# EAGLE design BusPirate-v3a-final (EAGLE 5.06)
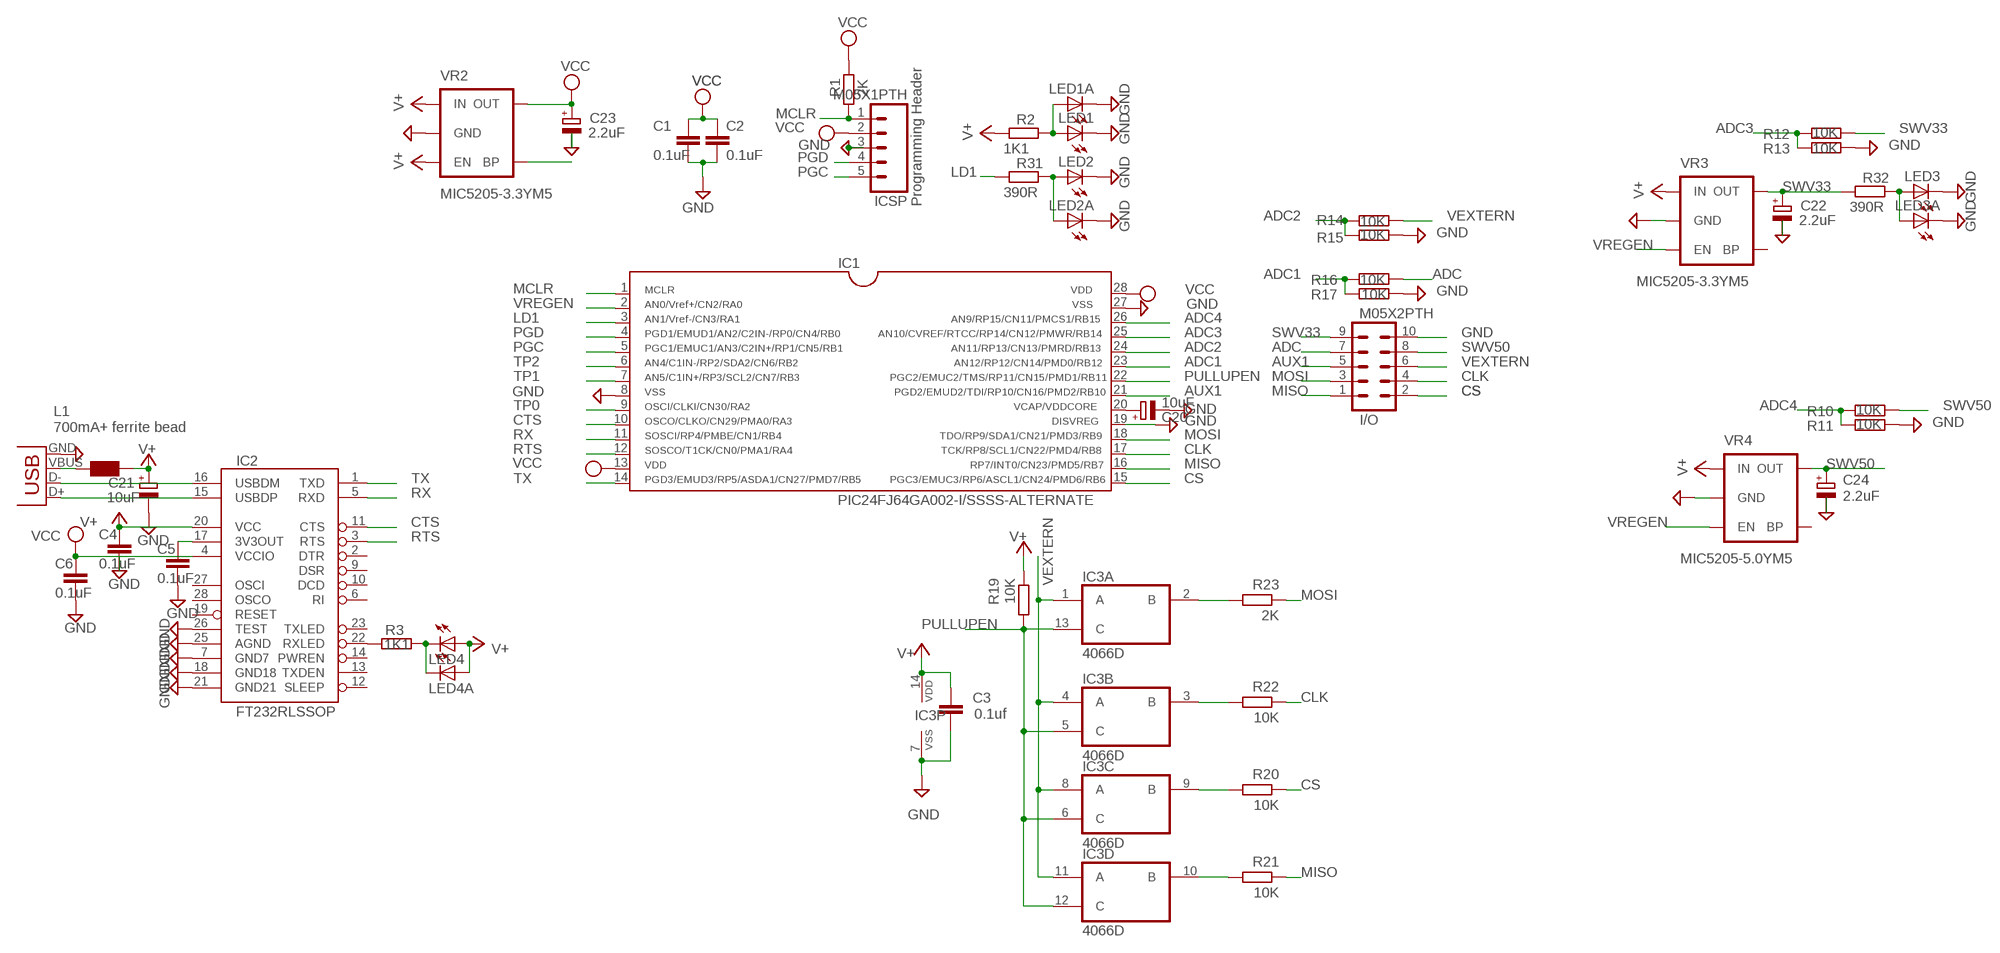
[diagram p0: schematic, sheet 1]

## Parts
C1  0.1uF  C-EUC0805  [C0805]
C2  0.1uF  C-EUC0805  [C0805]
C3  0.1uf  C-EUC0805  [C0805]
C4  0.1uF  C-EUC0805  [C0805]
C5  0.1uF  C-EUC0805  [C0805]
C6  0.1uF  C-EUC0805  [C0805]
C20  10uF  CPOL-EUSMCA  [SMC_A]
C21  10uF  CPOL-EUSMCA  [SMC_A]
C22  2.2uF  CPOL-EUSMCA  [SMC_A]
C23  2.2uF  CPOL-EUSMCA  [SMC_A]
C24  2.2uF  CPOL-EUSMCA  [SMC_A]
I/O  M05X2PTH  [AVR_ICSP]
IC1  PIC24FJ64GA002-I/SSSS-ALTERNATE  [SSOP28DB]
IC2  FT232RLSSOP  [SSOP28DB]
IC3  4066D  [SO14]
ICSP  M05X1PTH  M05  [1X05]
J1  USBSMD  [USB-MINIB]
L1  700mA+ ferrite bead  WE-KIL_0805  [WE-KI_0805_B]
LED1  LEDCHIP-LED0805  [CHIP-LED0805]
LED1A  LEDCHIP-LED0805  [CHIP-LED0805]
LED2  LEDCHIP-LED0805  [CHIP-LED0805]
LED2A  LEDCHIP-LED0805  [CHIP-LED0805]
LED3  LEDCHIP-LED0805  [CHIP-LED0805]
LED3A  LEDCHIP-LED0805  [CHIP-LED0805]
LED4  LEDCHIP-LED0805  [CHIP-LED0805]
LED4A  LEDCHIP-LED0805  [CHIP-LED0805]
R1  2K  R-EU_R0805  [R0805]
R2  1K1  R-EU_M0805  [M0805]
R3  1K1  R-EU_M0805  [M0805]
R10  10K  R-EU_M0805  [M0805]
R11  10K  R-EU_M0805  [M0805]
R12  10K  R-EU_M0805  [M0805]
R13  10K  R-EU_M0805  [M0805]
R14  10K  R-EU_M0805  [M0805]
R15  10K  R-EU_M0805  [M0805]
R16  10K  R-EU_M0805  [M0805]
R17  10K  R-EU_M0805  [M0805]
R19  10K  R-EU_R0805  [R0805]
R20  10K  R-EU_R0805  [R0805]
R21  10K  R-EU_R0805  [R0805]
R22  10K  R-EU_R0805  [R0805]
R23  2K  R-EU_R0805  [R0805]
R31  390R  R-EU_M0805  [M0805]
R32  390R  R-EU_M0805  [M0805]
VR2  MIC5205-3.3YM5  V_REG_LDOSMD  [SOT23-5]
VR3  MIC5205-3.3YM5  V_REG_LDOSMD  [SOT23-5]
VR4  MIC5205-5.0YM5  V_REG_LDOSMD  [SOT23-5]

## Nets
$N26: J1.VBUS L1.2
ADC: I/O.7 R16.1
ADC1: IC1.23 R16.2 R17.2
ADC2: IC1.24 R14.2 R15.2
ADC3: IC1.25 R12.2 R13.2
ADC4: IC1.26 R10.2 R11.2
AUX1: I/O.5 IC1.21
CLK: I/O.4 IC1.17 R22.1
CS: I/O.2 IC1.15 R20.1
CTS: IC1.10 IC2.11(CTS)
GND: C1.2 C2.2 C3.2 C4.2 C5.2 C6.2 C20.- C21.- C22.- C23.- C24.- I/O.10 IC1.8 IC1.19 IC1.27 IC2.7(GND7) IC2.18(GND18) IC2.21(GND21) IC2.25(AGND) IC2.26(TEST) IC3.7(P:VSS) ICSP.3 J1.GND LED1.C LED1A.C LED2.C LED2A.C LED3.C LED3A.C R11.1 R13.1 R15.1 R17.1 VR2.2(GND) VR3.2(GND) VR4.2(GND)
LD1: IC1.3 R31.2
MCLR: IC1.1 ICSP.1 R1.1
MISO: I/O.1 IC1.16 R21.1
MOSI: I/O.3 IC1.18 R23.1
N$1: IC3.2(A:B) R23.2
N$2: IC3.3(B:B) R22.2
N$3: C20.+ IC1.20
N$4: IC3.10(D:B) R21.2
N$5: IC3.9(C:B) R20.2
N$6: LED2.A LED2A.A R31.1
N$7: LED1.A LED1A.A R2.1
N$8: VR2.4(BP)
N$9: C5.1 IC2.17(3V3OUT)
N$11: IC2.22(RXLED) R3.2
N$13: LED4.C LED4A.C R3.1
N$15: IC2.15(USBDP) J1.D+
N$16: IC2.16(USBDM) J1.D-
N$18: LED3.A LED3A.A R32.1
PGC: IC1.5 ICSP.5
PGD: IC1.4 ICSP.4
PULLUPEN: IC1.22 IC3.5(B:C) IC3.6(C:C) IC3.12(D:C) IC3.13(A:C) R19.2
RTS: IC1.12 IC2.3(RTS)
RX: IC1.11 IC2.5(RXD)
SWV33: C22.+ I/O.9 R12.1 R32.2 VR3.5(OUT)
SWV50: C24.+ I/O.8 R10.1 VR4.5(OUT)
TP0: IC1.9
TP1: IC1.7
TP2: IC1.6
TX: IC1.14 IC2.1(TXD)
V+: C3.1 C4.1 C21.+ IC2.20(VCC) IC3.14(P:VDD) L1.1 LED4.A LED4A.A R2.2 R19.1 VR2.1(IN) VR2.3(EN) VR3.1(IN) VR4.1(IN)
VCC: C1.1 C2.1 C6.1 C23.+ IC1.13 IC1.28 IC2.4(VCCIO) ICSP.2 R1.2 VR2.5(OUT)
VEXTERN: I/O.6 IC3.1(A:A) IC3.4(B:A) IC3.8(C:A) IC3.11(D:A) R14.1
VREGEN: IC1.2 VR3.3(EN) VR4.3(EN)
Unconnected: IC2.2(DTR) IC2.6(RI) IC2.9(DSR) IC2.10(DCD) IC2.12(SLEEP) IC2.13(TXDEN) IC2.14(PWREN) IC2.19(RESET) IC2.23(TXLED) IC2.27(OSCI) IC2.28(OSCO) VR3.4(BP) VR4.4(BP)

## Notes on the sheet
- Programming Header

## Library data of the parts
C1-C6 = rcl:C-EU: CAPACITOR, European symbol
C20-C24 = rcl:CPOL-EU: POLARIZED CAPACITOR, European symbol
I/O = SparkFun:M05X2: Header 5x2 Standard 10-pin dual row 0.1" header. Commonly used with AVR-ISP. Use with Spark Fun Electronics SKU: PRT-00778
IC1 = microchip-pic24:PIC24FJ64GA002-I/SS
IC2 = SparkFun:FT232RL: USB UART FT232RL 4th Generation USB UART (USB <-> Serial) Controller. Spark Fun Electronics SKU : COM-00650
IC3 = 40xx:4066: Quad bilateral ANALOG SWITCH
ICSP = SparkFun:M05: Header 5 Standard 5-pin 0.1" header. Use with straight break away headers (SKU : PRT-00116), right angle break away headers (PRT-00553), swiss pins (PRT-00743), machine pins (PRT-00117), and female headers (PRT-00115). Molex polarized connector foot print use with SKU : PRT-08230 with associated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
J1 = SparkFun:USB: USB Connectors USB-B-PTH is fully proven SKU : PRT-00139 USB-miniB is fully proven SKU : PRT-00587 USB-A-PCB is untested. USB-A-H is throughly reviewed, but untested. Spark Fun Electronics SKU : PRT-00437 USB-B-SMT is throughly reviewed, but untested. Needs silkscreen touching up. USB-A-S has not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
L1 = wuerth-elektronik:WE-KIL: SMD Wire Wound Ceramic Inductor WE-KIL
LED1 LED1A LED2 LED2A LED3 LED3A LED4 LED4A = led:LED: LED
R1 R2 R19-R23 R31 R32 = rcl:R-EU_: RESISTOR, European symbol
R3 R10-R17 = resistor:R-EU_: RESISTOR, European symbol
VR2-VR4 = SparkFun:V_REG_LDO: Voltage Regulator LDO Standard 150mA LDO voltage regulator in SOT-23 layout. Micrel part MIC5205. BP (by-pass) pin is used to lower output noise with 470pF cap.

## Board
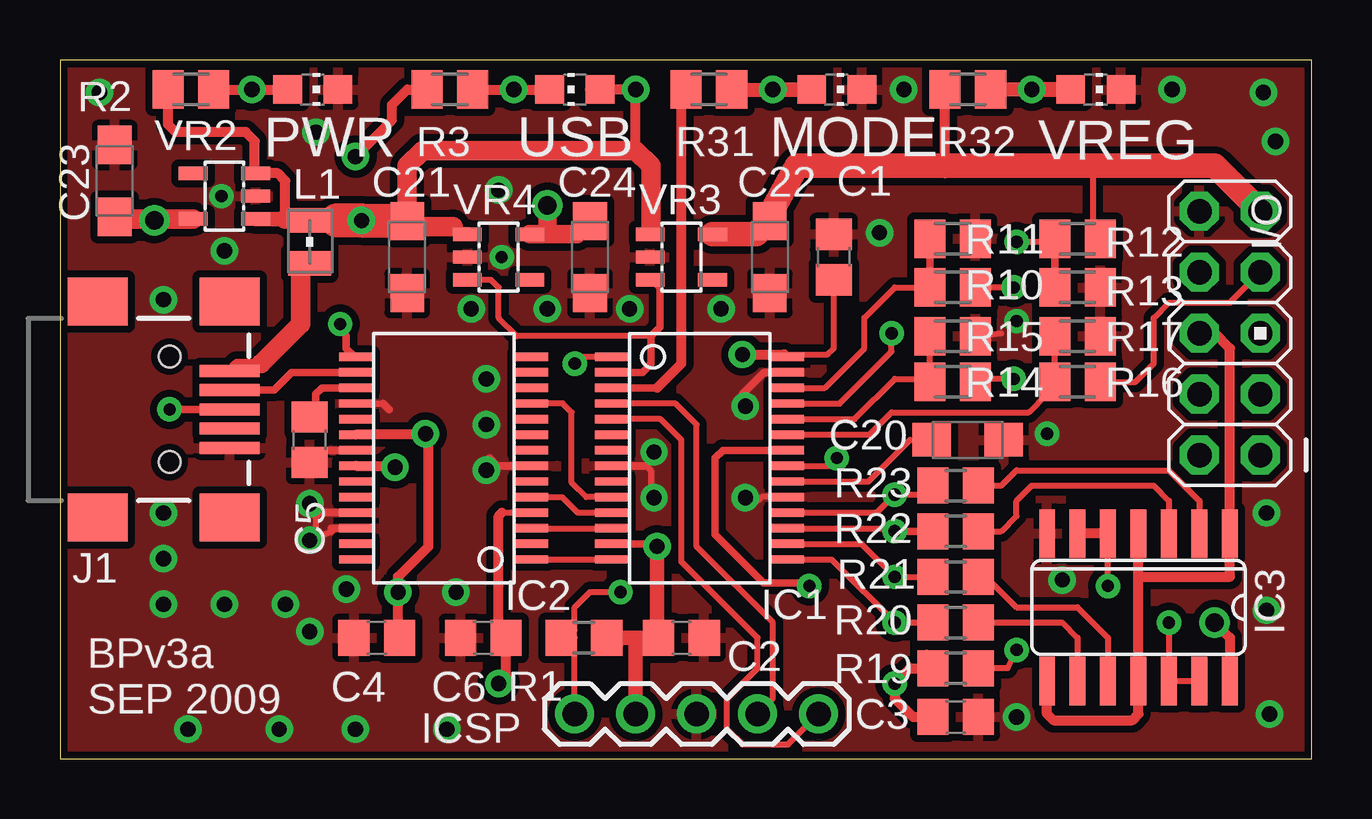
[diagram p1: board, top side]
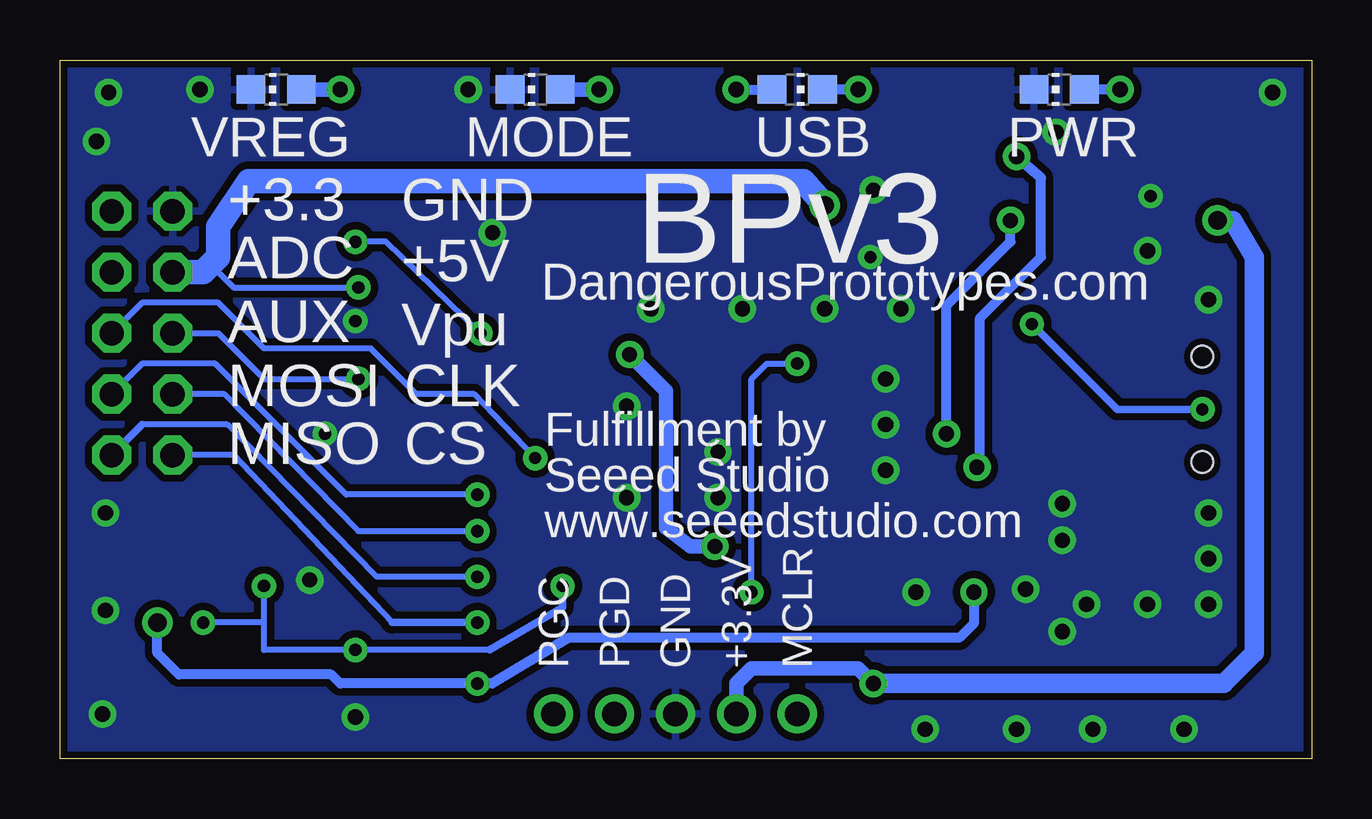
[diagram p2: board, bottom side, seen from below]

Size 52.19 x 29.13 mm. Coordinates in mm from the lower left corner, seen from the top.
Outline: 52.19,0 52.19,29.13 0,29.13 0,0 52.19,0
Copper layers (1*16): Top 0.035mm / dielectric 1.5mm / Bottom 0.035mm
Design rules "SparkFun": minimum track width 8mil, minimum drill 20mil, track to track 8mil, track to pad 8mil, pad to pad 8mil, via to via 8mil, smd to smd 8mil, copper to edge 10mil, drill to drill 8mil, minimum pad ring 12mil, minimum via ring 10mil, stop-mask expansion 4mil, vias tented up to drill 25mil, thermal gap 10mil
tRestrict: area 11.9,9.9 to 12.8,10

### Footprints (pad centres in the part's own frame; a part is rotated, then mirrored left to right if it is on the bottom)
C0805 = smd 1.3 x 1.5: 1 -0.95,0; 2 0.95,0
SMC_A = smd 1.6 x 1.4: + -1.5,0; - 1.5,0
AVR_ICSP = drill 1.016 octagon: 1 -1.27,5.08; 2 1.27,5.08; 3 -1.27,2.54; 4 1.27,2.54; 5 -1.27,0; 6 1.27,0; 7 -1.27,-2.54; 8 1.27,-2.54; 9 -1.27,-5.08; 10 1.27,-5.08
SSOP28DB = smd 0.348 x 1.397: 1 -4.225,-3.656; 2 -3.575,-3.656; 3 -2.925,-3.656; 4 -2.275,-3.656; 5 -1.625,-3.656; 6 -0.975,-3.656; 7 -0.325,-3.656; 8 0.325,-3.656; 9 0.975,-3.656; 10 1.625,-3.656; 11 2.275,-3.656; 12 2.925,-3.656; 13 3.575,-3.656; 14 4.225,-3.656; 15 4.225,3.656; 16 3.575,3.656; 17 2.925,3.656; 18 2.275,3.656; 19 1.625,3.656; 20 0.975,3.656; 21 0.325,3.656; 22 -0.325,3.656; 23 -0.975,3.656; 24 -1.625,3.656; 25 -2.275,3.656; 26 -2.925,3.656; 27 -3.575,3.656; 28 -4.225,3.656
SO14 = smd 0.66 x 2.032: 1 -3.81,-3.073; 2 -2.54,-3.073; 3 -1.27,-3.073; 4 0,-3.073; 5 1.27,-3.073; 6 2.54,-3.073; 7 3.81,-3.073; 8 3.81,3.073; 9 2.54,3.073; 10 1.27,3.073; 11 0,3.073; 12 -1.27,3.073; 13 -2.54,3.073; 14 -3.81,3.073
1X05 = drill 1.016 round: 1 0,0; 2 2.54,0; 3 5.08,0; 4 7.62,0; 5 10.16,0
USB-MINIB = smd 2.5 x 0.5: D+ 2.5,0; D- 2.5,0.8; GND 2.5,-1.6; ID 2.5,-0.8; VBUS 2.5,1.6 | smd 2.5 x 2: GND@1 -3,-4.5; GND@2 -3,4.5; GND@3 2.5,4.5; GND@4 2.5,-4.5 | hole 0.9: 0,2.2; 0,-2.2
WE-KI_0805_B = smd 1.02 x 1.78: 1 -0.89,0; 2 0.89,0
CHIP-LED0805 = smd 1.2 x 1.2: A 0,-1.05; C 0,1.05
R0805 = smd 1.3 x 1.5: 1 -0.95,0; 2 0.95,0
M0805 = smd 1.3 x 1.6: 1 -0.95,0; 2 0.95,0
SOT23-5 = smd 0.55 x 1.2: 1 -0.95,-1.3; 2 0,-1.3; 3 0.95,-1.3; 4 0.95,1.3; 5 -0.95,1.3

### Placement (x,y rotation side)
C1  32.25,20.92 90 top
C2  25.9,5.04 0 top
C3  37.33,1.74 0 top
C4  13.2,5.04 180 top
C5  10.41,13.3 270 top
C6  17.65,5.04 180 top
C20  37.84,13.3 0 top
C21  14.47,20.92 270 top
C22  29.59,20.92 270 top
C23  2.28,24.09 90 top
C24  22.09,20.92 270 top
I/O  48.76,17.74 180 top
IC1  26.66,12.54 270 top
IC2  16,12.54 90 top
IC3  44.95,6.31 180 top
ICSP  21.46,1.87 0 top
J1  4.57,14.57 0 top
L1  10.41,21.55 270 top
LED1  10.54,27.9 270 top
LED1A  10.54,27.9 90 bottom
LED2  32.38,27.9 270 top
LED2A  32.38,27.9 90 bottom
LED3  43.17,27.9 270 top
LED3A  43.17,27.9 90 bottom
LED4  21.46,27.9 90 top
LED4A  21.46,27.9 270 bottom
R1  21.84,5.04 0 top
R2  5.46,27.9 180 top
R3  16.25,27.9 180 top
R10  37.21,19.65 180 top
R11  37.21,21.68 180 top
R12  42.41,21.68 180 top
R13  42.41,19.65 180 top
R14  37.21,15.71 180 top
R15  37.21,17.61 180 top
R16  42.41,15.71 180 top
R17  42.41,17.61 180 top
R19  37.33,3.77 0 top
R20  37.33,5.68 0 top
R21  37.33,7.58 0 top
R22  37.33,9.49 0 top
R23  37.33,11.39 0 top
R31  27.05,27.9 180 top
R32  37.84,27.9 180 top
VR2  6.85,23.46 90 top
VR3  25.9,20.92 270 top
VR4  18.28,20.92 270 top

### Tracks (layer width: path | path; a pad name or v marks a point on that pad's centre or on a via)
$N26
  Top 0.406: 8.38,16.47 7.37,16.47 J1.VBUS
  Top 0.813: L1.2 10.03,20.41 10.03,18.12 8.38,16.47
ADC
  Top 0.254: I/O.7 48.76,19.01 46.22,19.01 45.59,18.38 45.59,16.47 44.83,15.71 R16.1
ADC1
  Top 0.254: R17.2 R16.2 41.46,15.2 41.14,15.2 40.38,14.44 34.67,14.44 33.74,13.51 IC1.23
ADC2
  Top 0.254: R15.2 R14.2 36.26,15.84 34.79,15.84 33.12,14.16 IC1.24
ADC3  (via drill 0.51)
  Top 0.254: v34.67,17.74 34.67,16.98 32.5,14.81 IC1.25 | v39.87,21.55 41.34,21.55 R12.2
  Top 0.305: R13.2 R12.2 41.46,21.87
  Bottom 0.254: v39.87,21.55 38.6,21.55 v34.67,17.74
ADC4
  Top 0.254: IC1.26 31.88,15.46 33.52,17.11 33.52,18.38 34.79,19.65 R10.2
  Top 0.305: R10.2 R11.2
  Top 0.406: R10.2 36.06,19.65
AUX1  (via drill 0.51)
  Top 0.254: IC1.21 32.05,12.21 v32.38,12.54
  Bottom 0.254: I/O.5 48.76,19.01 45.59,19.01 43.68,17.11 39.24,17.11 37.33,15.2 34.92,15.2 v32.38,12.54
CLK  (via drill 0.51)
  Top 0.254: IC1.17 34.67,9.61 v34.79,9.49
  Top 0.305: v34.79,9.49 R22.1
  Bottom 0.254: I/O.4 45.33,15.2 39.75,9.49 v34.79,9.49
CS  (via drill 0.51)
  Top 0.254: R20.1 v34.79,5.68 32.25,8.22 | 32.25,8.22 32.22,8.25 | IC1.15 32.16,8.31 32.25,8.22
  Bottom 0.254: I/O.2 44.95,12.66 38.35,5.68
  Bottom 0.305: v34.79,5.68 38.35,5.68
CTS
  Top 0.254: IC1.10 21.94,10.91 21.33,11.52 21.33,14.44 20.95,14.82 19.66,14.82 IC2.11
GND  (via drill 0.51, 0.64)
  Top 0.254: IC2.18 13.47,14.81 | R15.1 39.24,17.74 | 24.45,12.21 24.63,12.03 24.63,11.01 v24.76,10.88 | IC1.19 29.23,10.91 29.08,10.76 | 10.66,10.12 10.66,9.49 | v10.41,9.11 11.3,9.49
  Top 0.305: IC2.7 18.23,12.21 17.9,12.54 | 13.47,14.81 13.71,14.57 | IC1.27 29.35,16.11 28.44,15.2 28.44,14.82 v28.57,14.69 | IC1.8 24.45,12.21 | IC2.21 10.53,12.86 C5.2 | IC2.25 10.8,10.26 10.66,10.12 | IC2.26 11.3,9.61 11.3,9.49
  other vias: 41.78,7.45 50.29,6.18 50.41,1.87 41.14,13.55 39.87,18.25 34.16,21.93 4.31,10.25 4.31,19.14 35.17,27.9 28.57,10.88 39.87,1.74 50.29,10.25 50.67,25.74 23.74,18.76 20.32,18.76 18.28,23.71 17.14,18.76 17.77,15.84 4.31,6.44 12.31,1.23 4.31,8.34 10.41,10.63 24.76,12.79 10.66,26.12 27.55,18.76 18.41,20.92 5.33,1.23 50.16,27.78 46.35,27.9 9.39,6.44 17.77,12.03 17.77,13.93 6.85,6.44 1.65,27.78 16.5,6.95 10.41,5.3 9.14,1.23 16.12,1.23 11.93,7.07 6.73,23.46 6.85,21.17
  pour Top (isolate 0.305): 0.5,29.17 51.94,29.17 51.94,-0.04 0.5,-0.04
  pour Bottom (isolate 0.305): 0.5,29.17 51.94,29.17 51.94,-0.04 0.5,-0.04
LD1
  Top 0.305: IC1.3 24.89,15.46
  Top 0.406: 24.89,15.46 25.9,16.47 25.9,27.58 R31.2
MCLR  (via drill 0.51)
  Top 0.254: IC1.1 21.75,16.76 v21.46,16.47 | v23.36,6.95 22.09,6.95 21.46,6.31 21.46,5.36 R1.1 21.46,5.04 ICSP.1
  Bottom 0.254: v21.46,16.47 22.73,16.47 23.36,15.84 v23.36,6.95
MISO  (via drill 0.51)
  Top 0.254: v34.79,7.58 R21.1 | v34.79,7.58 34.69,7.69 | IC1.16 33.41,8.96 v34.79,7.58
  Bottom 0.254: 48.76,13.93 45.21,13.93 38.98,7.58 v34.79,7.58
  Bottom 0.305: 48.76,13.93 I/O.1
MOSI  (via drill 0.51)
  Top 0.254: IC1.18 34.04,10.26 v34.79,11.01 36,11.01 R23.1
  Bottom 0.254: I/O.3 48.76,16.47 45.72,16.47 40.25,11.01 v34.79,11.01
N$1
  Top 0.254: IC3.2 47.49,10.76 46.22,12.03 39.87,12.03 39.24,11.39 R23.2
N$2
  Top 0.254: R22.2 39.24,9.49 39.87,10.12 39.87,10.76 40.51,11.39 45.59,11.39 46.22,10.76 IC3.3
N$3
  Top 0.254: IC1.20 33.69,11.56 35.43,13.3 C20.+
N$4
  Top 0.254: R21.2 38.6,7.58 39.87,6.31 42.41,6.31 43.68,5.04 IC3.10
N$5
  Top 0.254: R20.2 41.78,5.68 42.41,5.04 IC3.9
N$6  (via drill 0.64)
  Top 0.406: R31.1 28.16,27.87
  Top 0.61: 28.16,27.87 LED2A.A v29.71,27.9
  Bottom 0.61: v29.71,27.9 LED2A.A
N$7  (via drill 0.64)
  Top 0.406: 6.22,27.9 R2.1 v8,27.9 LED1A.A
  Bottom 0.406: v8,27.9 LED1A.A
N$9
  Top 0.305: IC2.17 10.92,15.46 10.66,15.2 10.66,14.5 C5.1
N$11  (via drill 0.64)
  Top 0.406: 15.36,27.78 R3.2 14.47,27.9 13.84,27.27 13.84,26.63 v12.31,25.11 | IC2.22 13.91,12.21 v13.96,12.15
  Bottom 0.406: v12.31,25.11 11.3,24.22 11.3,20.92 13.84,18.38 13.84,12.15 v13.96,12.15
N$13  (via drill 0.64)
  Top 0.406: R3.1 v18.92,27.9 | v18.92,27.9 LED4A.C v18.92,27.9
  Bottom 0.406: v18.92,27.9 LED4A.C
N$15  (via drill 0.51)
  Top 0.305: v4.57,14.57 J1.D+ | IC2.15 12.28,16.76 11.93,17.11 11.93,17.61 v11.68,18.12
  Bottom 0.305: v4.57,14.57 8.12,14.57 v11.68,18.12
N$16
  Top 0.254: IC2.16 12.36,16.09
  Top 0.305: J1.D- 8.92,15.37 9.67,16.11 IC2.16
N$18  (via drill 0.64)
  Top 0.406: 42.1,27.93 LED3A.A
  Top 0.61: R32.1 42.1,27.93 | LED3A.A v40.51,27.9
  Bottom 0.61: v40.51,27.9 LED3A.A
PGC
  Top 0.254: IC1.5 25.04,14.16 25.9,13.3 25.9,8.22 29.08,5.04 29.08,3.77 27.81,2.5 27.81,1.23 28.44,0.6 30.35,0.6 ICSP.5
PGD
  Top 0.254: IC1.4 25.66,14.81 26.54,13.93 26.54,8.85 29.71,5.68 29.71,2.5 ICSP.4
PULLUPEN  (via drill 0.51)
  Top 0.254: v46.22,5.68 IC3.12 IC3.13 | v43.68,7.2 IC3.5 | R19.2 39.49,3.77 v39.87,4.53
  Top 0.305: IC1.22 27.62,12.86 27.3,12.54 27.3,9.36 29.33,7.33 31.11,7.33 v31.24,7.2
  Top 0.406: IC3.5 IC3.6
  Bottom 0.254: 43.68,5.68 43.68,4.53 v39.87,4.53 34.28,4.53 | 43.68,5.68 v43.68,7.2 | 43.68,5.68 v46.22,5.68
  Bottom 0.305: v31.24,7.2 31.24,6.31 34.28,4.53
RTS
  Top 0.254: IC2.3 IC1.12
RX
  Top 0.254: IC1.11 21.57,10.26 20.92,10.91 IC2.5
SWV33
  Top 0.254: R12.1 43.05,21.55 43.05,24.73
  Top 0.406: 37.02,27.9 R32.2 36.89,24.41 36.7,24.73
  Top 0.61: C22.+ 29.59,22.69
  Top 1.016: VR3.5 29.04,21.87 C22.+ | 29.59,22.69 30.73,24.73 36.7,24.73 43.05,24.73 48.13,24.73 I/O.9
SWV50  (via drill 0.51, 0.76)
  Top 0.254: v39.75,19.65 R10.1 | C24.+ 22.09,22.19
  Top 0.61: 21.54,21.87 C24.+ | 20.19,21.87 20.32,21.99
  Top 0.762: VR4.5 20.19,21.87 21.54,21.87 | 20.32,21.99 v20.32,23.08
  Bottom 0.254: v39.75,19.65 44.95,19.65 45.91,20.6
  Bottom 1.016: v20.32,23.08 21.2,24.09 44.32,24.09 45.59,22.19 45.59,20.92 45.91,20.6 46.22,20.28 I/O.8
TX
  Top 0.254: IC2.1 IC1.14
V+  (via drill 0.51, 0.64, 0.76)
  Top 0.254: IC3.14 48.76,2.82 | 36.13,4.34 R19.1 36.38,3.45
  Top 0.406: C4.1 14.09,5.74 14.09,7.58 | 36.13,4.34 36.13,3.84 36.06,3.77 35.43,3.77 v34.79,3.14 34.79,2.5 35.55,1.74 C3.1 | 14.09,7.58 v14.09,6.95 | 14.09,7.58 15.36,8.85 15.36,13.42 v15.23,13.55 | IC3.14 48.76,5.04 v48.13,5.68 | 22.09,27.9 LED4A.A v24,27.9 24,25.36 | 9.39,22.51 9.39,24.09 9.08,24.41 VR2.3 8.12,24.44 8.12,25.74 7.74,26.12 4.82,26.12 4.51,26.44 R2.2 | v15.23,13.55 15.11,13.55 | IC2.20 15.19,13.51 v15.23,13.55
  Top 0.61: 9.39,22.51 VR2.1 | VR4.1 16.7,21.87 16.38,22.19 | VR3.1 24.6,22.16 24.63,22.19
  Top 0.813: 14.47,22.44 14.47,24.73 15.11,25.36 24,25.36 24.63,24.73 24.63,22.19 | 16.38,22.19 14.7,22.19 C21.+ | 9.39,22.51 10.34,22.51 L1.1
  Top 1.016: 14.47,22.44 C21.+ | v12.57,22.44 | L1.1 11.55,22.44
  Top 1.422: 14.47,22.44 v12.57,22.44 11.55,22.44
  Bottom 0.406: v48.13,5.68 48.13,4.41 47.24,3.52 40.89,3.52 40.51,3.14 v34.79,3.14 34.16,3.14 30.98,5.04 14.7,5.04 14.1,5.64 v14.1,6.94 v14.09,6.95 | v24,27.9 LED4A.A | v15.23,13.55 15.23,18.89 12.57,21.55 v12.57,22.44
VCC  (via drill 0.64, 0.76)
  Top 0.254: R1.2 23.36,4.72 | 30.2,16.85 32,16.85 32.25,17.11 C1.1 | 18.42,10.26 IC2.4 | C6.1 18.28,5.36
  Top 0.305: IC1.13 24.78,8.96 v24.89,8.85 | 30.2,16.85 30.23,16.85 IC1.28
  Top 0.406: 25.27,5.36 C2.1 24.89,5.36 | v24.89,8.85 24.52,8.96 | v28.44,16.85 30.2,16.85 | 18.42,10.26 18.28,10.12 18.28,5.36 | C6.1 18.6,3.45 v18.28,3.14
  Top 0.61: 24,5.04 R1.2 | 24,5.04 C2.1 | 24.89,5.36 v24.89,8.85 | ICSP.2 24,5.04
  Top 0.813: C23.+ 2.49,22.51 VR2.5 4.25,22.51 v3.93,22.44
  Bottom 0.61: ICSP.2 24,3.14 23.36,3.77 18.92,3.77 v18.28,3.14 | v24.89,8.85 25.9,8.85 26.92,9.61 26.92,15.33 v28.44,16.85
  Bottom 0.813: v3.93,22.44 3.3,22.44 2.41,20.92 2.41,4.41 3.68,3.14 v18.28,3.14
VEXTERN  (via drill 0.51)
  Top 0.254: v39.75,15.84 38.28,15.84 R14.1
  Top 0.406: 44.95,7.58 48.76,7.58 IC3.1 48.76,17.11 48.13,17.74 I/O.6 | IC3.8 41.14,1.87 41.4,1.61 44.7,1.61 44.95,1.87 IC3.11 44.95,7.58 | 44.95,7.58 IC3.4
  Bottom 0.254: I/O.6 45.59,17.74 43.68,15.84 v39.75,15.84
VREGEN
  Top 0.254: VR4.3 17.96,19.97 18.28,19.65 18.28,18.38 19.05,17.61 24.63,17.61
  Top 0.305: VR3.3 24.63,19.94 24.72,19.94 25.01,19.65 25.01,18 24.63,17.61 24.63,16.47 24.27,16.11 IC1.2

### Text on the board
tNames: PWR | USB | MODE | VREG | BPv3a | SEP 2009
bNames: PWR | USB | MODE | VREG | GND | +3.3 | BPv3 | +5V | ADC | DangerousPrototypes.com | Vpu | AUX | CLK | MOSI | Fulfillment by | CS | MISO | Seeed Studio | www.seeedstudio.com | MCLR | +3.3V | GND | PGD | PGC
Reference: GND | +3v | +5v | ADC | Vpu | AUX1 | CLK | MOSI | USB | CS | MISO | I/O header | MCLR | +3.3V | GND | DATA | CLOCK | Programming Header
